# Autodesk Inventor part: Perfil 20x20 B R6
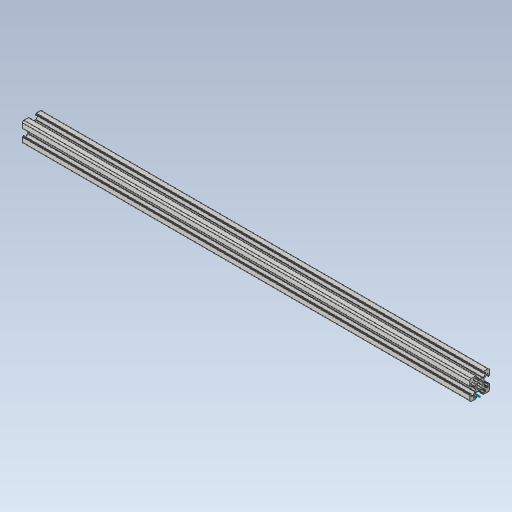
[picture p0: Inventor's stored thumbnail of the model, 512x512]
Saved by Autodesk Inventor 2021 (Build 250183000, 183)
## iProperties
Created: 2020-12
Part Number: Perfil 20x20 B R6
Material: Genérico
Document SubType Name: Modeling
Designer: ATOUZA
Density: 1 g/cm^3
Appearance: Valor por defecto
Author: ATOUZA
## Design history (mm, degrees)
sketch "Boceto1"
  geometry: L1 (4.5, 0.954)-(4.5, 3.232); L2 (4.646, 3.586)-(6.914, 5.854); L3 (7.268, 6)-(8, 6); L4 (8.5, 5.5)-(8.5, 3.6); L5 (9, 3.1)-(9.3, 3.1); L6 (9.5, 3.3)-(9.5, 3.65); L7 (9.5, 3.65)-(9.8, 3.65); L8 (10, 3.85)-(10, 8.5); L9 (8.5, 10)-(3.85, 10); L10 (3.65, 9.8)-(3.65, 9.5); L11 (3.65, 9.5)-(3.3, 9.5); L12 (3.1, 9.3)-(3.1, 9); L13 (3.6, 8.5)-(5.5, 8.5); L14 (6, 8)-(6, 7.268); L15 (5.854, 6.914)-(3.586, 4.646); L16 (3.232, 4.5)-(0.954, 4.5); L17 (0.854, 4.473)-(0.1, 4.038); L18 (-0.1, 4.038)-(-0.854, 4.473); L19 (-0.954, 4.5)-(-3.232, 4.5); L20 (-3.586, 4.646)-(-5.854, 6.914); L21 (-6, 7.268)-(-6, 8); L22 (-5.5, 8.5)-(-3.6, 8.5); L23 (-3.1, 9)-(-3.1, 9.3); L24 (-3.3, 9.5)-(-3.65, 9.5); L25 (-3.65, 9.5)-(-3.65, 9.8); L26 (-3.85, 10)-(-8.5, 10); L27 (-10, 8.5)-(-10, 3.85); L28 (-9.8, 3.65)-(-9.5, 3.65); L29 (-9.5, 3.65)-(-9.5, 3.3); L30 (-9.3, 3.1)-(-9, 3.1); L31 (-8.5, 3.6)-(-8.5, 5.5); L32 (-8, 6)-(-7.268, 6); L33 (-6.914, 5.854)-(-4.646, 3.586); L34 (-4.5, 3.232)-(-4.5, 0.954); L35 (-4.473, 0.854)-(-4.038, 0.1); L36 (-4.038, -0.1)-(-4.473, -0.854); L37 (-4.5, -0.954)-(-4.5, -3.232); L38 (-4.646, -3.586)-(-6.914, -5.854); L39 (-7.268, -6)-(-8, -6); L40 (-8.5, -5.5)-(-8.5, -3.6); L41 (-9, -3.1)-(-9.3, -3.1); L42 (-9.5, -3.3)-(-9.5, -3.65); L43 (-9.5, -3.65)-(-9.8, -3.65); L44 (-10, -3.85)-(-10, -8.5); L45 (-8.5, -10)-(-3.85, -10); L46 (-3.65, -9.8)-(-3.65, -9.5); L47 (-3.65, -9.5)-(-3.3, -9.5); L48 (-3.1, -9.3)-(-3.1, -9); L49 (-3.6, -8.5)-(-5.5, -8.5); L50 (-6, -8)-(-6, -7.268); L51 (-5.854, -6.914)-(-3.586, -4.646); L52 (-3.232, -4.5)-(-0.954, -4.5); L53 (1.258, -2.445)-(1.914, -2.99); L54 (2.992, -1.91)-(2.445, -1.258); L55 (2.445, 1.258)-(2.992, 1.91); L56 (1.914, 2.99)-(1.258, 2.445); L57 (-1.258, 2.445)-(-1.914, 2.99); L58 (-2.992, 1.91)-(-2.445, 1.258); L59 (-2.445, -1.258)-(-2.992, -1.91); L60 (-1.914, -2.99)-(-1.258, -2.445); L61 (1.258, -2.445)-(1.914, -2.99); L62 (2.992, -1.91)-(2.445, -1.258); L63 (2.445, 1.258)-(2.992, 1.91); L64 (1.914, 2.99)-(1.258, 2.445)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; A1 r 0.5 centre (5, 3.232) between (4.646, 3.586) and (4.5, 3.232); A2 r 0.5 centre (7.268, 5.5) between (7.268, 6) and (6.914, 5.854); A3 r 0.5 centre (8, 5.5) between (8.5, 5.5) and (8, 6); A4 r 0.5 centre (9, 3.6) between (8.5, 3.6) and (9, 3.1); A5 r 0.2 centre (9.3, 3.3) between (9.3, 3.1) and (9.5, 3.3); A6 r 0.2 centre (9.8, 3.85) between (9.8, 3.65) and (10, 3.85); A7 r 1.5 centre (8.5, 8.5) between (10, 8.5) and (8.5, 10); A8 r 0.2 centre (3.85, 9.8) between (3.85, 10) and (3.65, 9.8); A9 r 0.2 centre (3.3, 9.3) between (3.3, 9.5) and (3.1, 9.3); A10 r 0.5 centre (3.6, 9) between (3.1, 9) and (3.6, 8.5); A11 r 0.5 centre (5.5, 8) between (6, 8) and (5.5, 8.5); A12 r 0.5 centre (5.5, 7.268) between (5.854, 6.914) and (6, 7.268); A13 r 0.5 centre (3.232, 5) between (3.232, 4.5) and (3.586, 4.646); A14 r 0.2 centre (0.954, 4.3) between (0.954, 4.5) and (0.854, 4.473); A15 r 0.2 centre (0, 4.211) between (-0.1, 4.038) and (0.1, 4.038); A16 r 0.2 centre (-0.954, 4.3) between (-0.854, 4.473) and (-0.954, 4.5); A17 r 0.5 centre (-3.232, 5) between (-3.586, 4.646) and (-3.232, 4.5); A18 r 0.5 centre (-5.5, 7.268) between (-6, 7.268) and (-5.854, 6.914); A19 r 0.5 centre (-5.5, 8) between (-5.5, 8.5) and (-6, 8); A20 r 0.5 centre (-3.6, 9) between (-3.6, 8.5) and (-3.1, 9); A21 r 0.2 centre (-3.3, 9.3) between (-3.1, 9.3) and (-3.3, 9.5); A22 r 0.2 centre (-3.85, 9.8) between (-3.65, 9.8) and (-3.85, 10); A23 r 1.5 centre (-8.5, 8.5) between (-8.5, 10) and (-10, 8.5); A24 r 0.2 centre (-9.8, 3.85) between (-10, 3.85) and (-9.8, 3.65); A25 r 0.2 centre (-9.3, 3.3) between (-9.5, 3.3) and (-9.3, 3.1); A26 r 0.5 centre (-9, 3.6) between (-9, 3.1) and (-8.5, 3.6); A27 r 0.5 centre (-8, 5.5) between (-8, 6) and (-8.5, 5.5); A28 r 0.5 centre (-7.268, 5.5) between (-6.914, 5.854) and (-7.268, 6); A29 r 0.5 centre (-5, 3.232) between (-4.5, 3.232) and (-4.646, 3.586); A30 r 0.2 centre (-4.3, 0.954) between (-4.5, 0.954) and (-4.473, 0.854); A31 r 0.2 centre (-4.211, 0) between (-4.038, -0.1) and (-4.038, 0.1); A32 r 0.2 centre (-4.3, -0.954) between (-4.473, -0.854) and (-4.5, -0.954); A33 r 0.5 centre (-5, -3.232) between (-4.646, -3.586) and (-4.5, -3.232); A34 r 0.5 centre (-7.268, -5.5) between (-7.268, -6) and (-6.914, -5.854); A35 r 0.5 centre (-8, -5.5) between (-8.5, -5.5) and (-8, -6); A36 r 0.5 centre (-9, -3.6) between (-8.5, -3.6) and (-9, -3.1); A37 r 0.2 centre (-9.3, -3.3) between (-9.3, -3.1) and (-9.5, -3.3); A38 r 0.2 centre (-9.8, -3.85) between (-9.8, -3.65) and (-10, -3.85); A39 r 1.5 centre (-8.5, -8.5) between (-10, -8.5) and (-8.5, -10); A40 r 0.2 centre (-3.85, -9.8) between (-3.85, -10) and (-3.65, -9.8); A41 r 0.2 centre (-3.3, -9.3) between (-3.3, -9.5) and (-3.1, -9.3); A42 r 0.5 centre (-3.6, -9) between (-3.1, -9) and (-3.6, -8.5); A43 r 0.5 centre (-5.5, -8) between (-6, -8) and (-5.5, -8.5); A44 r 0.5 centre (-5.5, -7.268) between (-5.854, -6.914) and (-6, -7.268); A45 r 0.5 centre (-3.232, -5) between (-3.232, -4.5) and (-3.586, -4.646); A46 r 2.75 centre (0, 0) between (-1.258, -2.445) and (1.258, -2.445); A47 r 3.55 centre (0, 0) between (1.914, -2.99) and (2.992, -1.91); A48 r 2.75 centre (0, 0) between (2.445, -1.258) and (2.445, 1.258); A49 r 3.55 centre (0, 0) between (2.992, 1.91) and (1.914, 2.99); A50 r 2.75 centre (0, 0) between (1.258, 2.445) and (-1.258, 2.445); A51 r 3.55 centre (0, 0) between (-1.914, 2.99) and (-2.992, 1.91); A52 r 2.75 centre (0, 0) between (-2.445, 1.258) and (-2.445, -1.258); A53 r 3.55 centre (0, 0) between (-2.992, -1.91) and (-1.914, -2.99); A54 r 2.75 centre (0, 0) between (-1.258, -2.445) and (1.258, -2.445); A55 r 3.55 centre (0, 0) between (1.914, -2.99) and (2.992, -1.91); A56 r 2.75 centre (0, 0) between (2.445, -1.258) and (2.445, 1.258); A57 r 3.55 centre (0, 0) between (2.992, 1.91) and (1.914, 2.99); A58 r 2.75 centre (0, 0) between (1.258, 2.445) and (-1.258, 2.445); A59 r 3.55 centre (0, 0) between (-1.914, 2.99) and (-2.992, 1.91); A60 r 2.75 centre (0, 0) between (-2.445, 1.258) and (-2.445, -1.258); A61 r 3.55 centre (0, 0) between (-2.992, -1.91) and (-1.914, -2.99); A62 r 0.5 centre (-8, -5.5) between (-8.5, -5.5) and (-8, -6); A63 r 0.2 centre (-4.211, 0) between (-4.038, -0.1) and (-4.038, 0.1); A64 r 0.5 centre (-7.268, 5.5) between (-6.914, 5.854) and (-7.268, 6)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; 1 further point
  constraints: 324 end point, 198 point on circle, 99 centre point, 2 point on line, 6 other
extrude "Extrusión1" new body sketch "Boceto1" distance "d0" = 450; taper "d1" = 0 deg
sketch "Boceto3"
  geometry: L1 (0, -3.85)-(450, -3.95); L2 (0, -3.95)-(450, -3.95) reference
  constraints: 2 end point, 1 parallel
node "Sólido1"
